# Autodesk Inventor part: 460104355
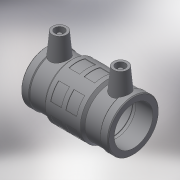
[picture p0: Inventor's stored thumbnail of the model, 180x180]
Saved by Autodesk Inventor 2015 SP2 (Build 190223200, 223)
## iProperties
Created: 2017-06
Part Number: 460104355
Material: Generic
Description: PLASSON LIGHTFIT COUPLER 355
Document SubType Name: Modeling
Designer: KIM
Mass: 89.5427 g
Surface Area: 304.58 cm^2
Volume: 89.5427 cm^3
Density: 1 g/cm^3
Appearance: Default
Author: KIM
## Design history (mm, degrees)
derived "460104.ipt"
feature "Solid1::460104.ipt"
tag "TaggingFeature1"
body "Solid1"
other parameters: "d14" = 17.6296, "d15" = 138, "d16" = 138, "d17" = 351.45, "d18" = 355, "d19" = 3.52592, "d20" = 168 deg, "d22" = 395.74, "d23" = 421, "d24" = 383.8678, "d25" = 135 deg, "d26" = 112, "d27" = 135 deg, "d29" = 204, "d35" = 15, "d39" = 5 deg, "d44" = 4, "d46" = 14, "d47" = 0, "d52" = 412.58, "d53" = 14, "d54" = 14, "d55" = 14, "d56" = 35 deg, "d58" = 360 deg, "d60" = 27.6, "d61" = 135 deg, "d62" = 126, "d63" = 3, "d64" = 0, "d_" = 355, "L_1" = 138, "D_" = 421, "A_" = 204, "d_2" = 12
